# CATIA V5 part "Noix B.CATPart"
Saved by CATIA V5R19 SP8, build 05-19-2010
Part number: Noix B
Bounding box of the stored display mesh (mm): x -98 to 0, y 0 to 5, z -23.5 to 16.5
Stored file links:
  F:\CFAO\Hberriche\Noix B.CATPart
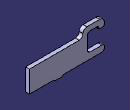
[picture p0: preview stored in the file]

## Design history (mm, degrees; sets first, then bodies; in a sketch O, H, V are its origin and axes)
Body1 (main body)
  Sketch1 on zx-plane, origin (0, 0, 0), H (-1, 0, 0), V (0, 0, 1)
    line L1 (0, 6.2916) -> (65, 6.2916)
    point P1 (0, 6.2916)
    point P2 (70, 6.2916)
    line L2 (70, 11.2916) -> (70, 11.5)
    point P3 (70, 16.5)
    line L3 (75, 16.5) -> (92, 16.5)
    point P4 (98, 16.5)
    line L4 (98, 10.5) -> (98, 8)
    point P5 (98, 6.5)
    point P6 (98, 6.5)
    line L5 (76, 7) -> (76, -11)
    line L6 (79, -14) -> (95, -14)
    point P7 (98, -14)
    line L7 (98, -17) -> (98, -19)
    point P8 (98, -22)
    line L8 (95, -22) -> (44, -22)
    line L9 (42.5, -23.5) -> (33.5, -23.5)
    point P9 (32, -22)
    line L10 (32, -22) -> (0, -22)
    line L11 (0, -22) -> (0, 6.2916)
    point P11 (0, 6.2916)
    arc A1 centre (75, 11.5) radius 5 from (70, 11.5) to (75, 16.5) cw
    arc A2 centre (92, 10.5) radius 6 from (92, 16.5) to (98, 10.5) cw
    arc A3 centre (96, 8) radius 2 from (96, 6) to (98, 8) ccw
    point P21 (76, 10)
    arc A4 centre (79, -11) radius 3 from (76, -11) to (79, -14) ccw
    arc A5 centre (95, -17) radius 3 from (95, -14) to (98, -17) cw
    arc A6 centre (95, -19) radius 3 from (95, -22) to (98, -19) ccw
    arc A7 centre (65, 11.2916) radius 5 from (70, 11.2916) to (65, 6.2916) cw
    arc A8 centre (32, -22.5) radius 0.5 from (32, -22) to (32.5, -22.5) cw
    point P35 (32.5, -22.5)
    arc A9 centre (44, -22.5) radius 0.5 from (43.5, -22.5) to (44, -22) cw
    point P37 (43.5, -22.5)
    arc A10 centre (33.5, -22.5) radius 1 from (33.5, -23.5) to (32.5, -22.5) cw
    point P41 (32.5, -22.5)
    arc A11 centre (42.5, -22.5) radius 1 from (42.5, -23.5) to (43.5, -22.5) ccw
    point P44 (43.5, -22.5)
    line L12 (96, 6) -> (91, 6)
    point P46 (91, 6)
    line L13 (88, 10) -> (79, 10)
    point P47 (76, 10)
    line L14 (91, 7) -> (91, 6)
    point P48 (91, 6)
    arc A12 centre (79, 7) radius 3 from (79, 10) to (76, 7) ccw
    arc A13 centre (88, 7) radius 3 from (88, 10) to (91, 7) cw
    distance L3 H = 16.5
    distance P3 P4 = 28
    radius A1 = 5
    distance P4 P5 = 10
    radius A2 = 6
    radius A3 = 2
    radius A4 = 3
    distance P7 P8 = 8
    radius A5 = 3
    radius A6 = 3
    distance P1 P2 = 70
    radius A7 = 5
    radius A8 = 0.5
    radius A10 = 1
    radius A11 = 1
    distance L12 L6 = 20
    radius A12 = 3
    radius A13 = 3
    length L13 = 9
    length L12 = 5
    length L5 = 18
    length L10 = 32
    length L8 = 51
    horizontal: L1 H, L3 H, L6 H, L8 H, L9 H, L10 H, L13 H
    vertical: L2 V, L4 V, L5 V, L7 V, L11 V, L14 V
    coincidence: P6 L4, P7 L4, P9 L8, P11 L1, P1 P11, P5 P6, L11 V, L2 P3, L3 P3, L3 P4, L4 P4, L4 P5, L6 P7, L7 P7, L8 P8, L7 P8, L2 P2, L1 P2, L10 P9, P35 P41, P37 P44, P47 L5, P21 P47, P48 P46, L13 P47, L5 P21
    tangency: A1 L2, A1 L3, A2 L3, A2 L4, A3 L4, A4 L5, A4 L6, A5 L6, A5 L7, A6 L8, A6 L7, A7 L2, A7 L1, A8 L10, A9 L8, A10 L9, A11 L9, L12 A3, A12 L13, A12 L5, A13 L13, A13 L14
  Pad1: profile Sketch1, direction (0, 1, 0), length 5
